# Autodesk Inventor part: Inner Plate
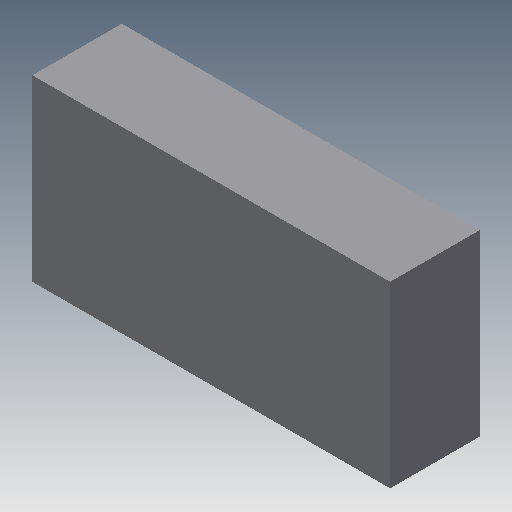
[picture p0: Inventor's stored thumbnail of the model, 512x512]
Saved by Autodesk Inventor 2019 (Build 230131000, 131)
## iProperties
Created: 2010-04
Part Number: Inner Plate
Document SubType Name: Modeling
Designer: CADSoft
Density: 1 g/cm^3
Material: Generic
Appearance: Default
Author: CADSoft
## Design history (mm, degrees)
sketch "Sketch1"
  geometry: L1 (-20.23, -7.511)-(19.77, -7.511); L2 (19.77, -7.511)-(19.77, 12.489); L3 (19.77, 12.489)-(-20.23, 12.489); L4 (-20.23, 12.489)-(-20.23, -7.511); 1 further point
  constraints: 8 end point, 2 parallel, 1 horizontal, 1 perpendicular
workplane "Work Plane1"
extrude "Extrusion1" new body sketch "Sketch1" stored distance "d0" = 25.4; taper "d1" = 0 deg
body "Solid1"
